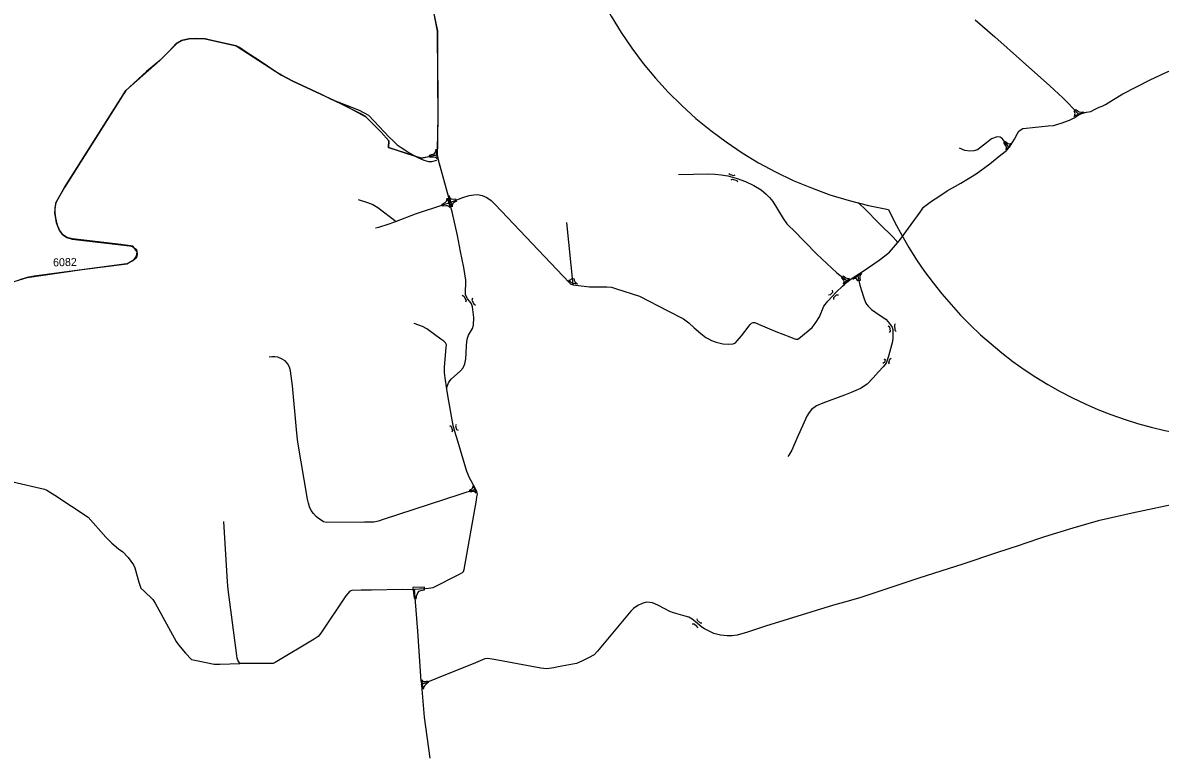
# Model space of a CAD drawing. Extents: x -444937 to -440733, y -1145714 to -1129798.
# Drawn here: x -443173 to -441752, y -1132712 to -1131804 of the extents above; entities that cross this region are included whole.
import ezdxf

# ---------------------------------------------------------------- set-up
doc = ezdxf.new("R2010")
doc.units = 0
for name, color, linetype in [('NIGP_sesuv_uz_P', 7, 'Continuous'), ('Vrstva 12', 7, 'Continuous'), ('Vrstva 75', 7, 'Continuous'), ('Vrstva 8', 7, 'Continuous'), ('Vrstva 84', 7, 'Continuous')]:
    doc.layers.add(name, color=color, linetype=linetype)

msp = doc.modelspace()

# ---------------------------------------------------------------- linework, layer by layer
at = {"layer": 'NIGP_sesuv_uz_P'}
for centre, start, end in [((-442005.1, -1131544.8), 171.1162, 260.1073), ((-441638.4, -1131824.9), 205.1413, 269.9118)]:
    msp.add_arc(centre, 500, start, end, dxfattribs=at)
at = {"layer": 'Vrstva 12'}
msp.add_line((-442485.1, -1132131.6), (-442492.7, -1132053.5), dxfattribs=at)
for points in [[(-441982.7, -1131800.5), (-441958.2, -1131821.9), (-441923.5, -1131852.4), (-441889.7, -1131882.8), (-441873.4, -1131897.8), (-441866.7, -1131904.6), (-441860.5, -1131911.2), (-441854.3, -1131917.8)], [(-442654.8, -1131969.1), (-442667.5, -1131971.9), (-442674.7, -1131973.3), (-442684, -1131970.4), (-442715.8, -1131960), (-442715.4, -1131951.4), (-442724.6, -1131940.9), (-442743.9, -1131921.6), (-442750.9, -1131917.6), (-442761.2, -1131912.4), (-442774.5, -1131905.7), (-442788.4, -1131899.3), (-442800.1, -1131893.4), (-442835.1, -1131877.3), (-442849.1, -1131869.7), (-442856.2, -1131865.4), (-442877.2, -1131851.4), (-442893.4, -1131840.9), (-442901.8, -1131835.2), (-442906.1, -1131832.8), (-442934.3, -1131826.6), (-442944.6, -1131824.4), (-442956.8, -1131823.9), (-442965.2, -1131824.1), (-442974.3, -1131826.4), (-442980.8, -1131830.2), (-442989.2, -1131839.1), (-443001.4, -1131851.4), (-443018.1, -1131865.1), (-443039.1, -1131884.4), (-443043.7, -1131888.6), (-443045.2, -1131890.8), (-443047.1, -1131893.7), (-443052.5, -1131902.5), (-443120.3, -1132010), (-443128.4, -1132023.4), (-443131.1, -1132029.1), (-443132.4, -1132035.3), (-443132.4, -1132041.5), (-443131.5, -1132047.9), (-443129.5, -1132056.9), (-443126.9, -1132063.3), (-443122.7, -1132068.7), (-443117.5, -1132072.3), (-443110.9, -1132074.3), (-443039.3, -1132082.5), (-443035.6, -1132083.6), (-443033.7, -1132084.6), (-443031.1, -1132086.9), (-443030.1, -1132088.9), (-443029.5, -1132093.4), (-443030, -1132095.5), (-443030.9, -1132097.9), (-443035.2, -1132101.5), (-443042.3, -1132105.1), (-443158.1, -1132120.6), (-443167, -1132122.3), (-443176.2, -1132125.1)], [(-442788.4, -1131899.3), (-442752.4, -1131913.4), (-442740.7, -1131919.7), (-442733.4, -1131926.9), (-442714.6, -1131947.1), (-442710, -1131951.8), (-442705, -1131956.7), (-442699.8, -1131960), (-442688.8, -1131966.8), (-442678.8, -1131972.6), (-442671.4, -1131975.8), (-442665.8, -1131977.2), (-442661.5, -1131977.2), (-442655.1, -1131975.8)], [(-441940.7, -1131959.3), (-441949.2, -1131948.5), (-441951.7, -1131946.9), (-441955.8, -1131946.8), (-441959.9, -1131948.2), (-441962.4, -1131949.3), (-441968.7, -1131954.2), (-441979.9, -1131962.7), (-441984.5, -1131963.9), (-441989.6, -1131964.5), (-441995.8, -1131963.6), (-442002.2, -1131960.7)], [(-442353.3, -1131993.5), (-442315.8, -1131992.9), (-442308, -1131993.2), (-442299.9, -1131994.2), (-442291.9, -1131995.5), (-442280.1, -1131998.6), (-442269.5, -1132002.4), (-442259.2, -1132007.5), (-442250.3, -1132012.8), (-442243.8, -1132018.1), (-442239.9, -1132022.3), (-442235.7, -1132027.5), (-442222.5, -1132048.4), (-442217.9, -1132055.2), (-442214.9, -1132058.7), (-442210.3, -1132062.9), (-442180.5, -1132092.9), (-442155.4, -1132116.3), (-442142.2, -1132127)], [(-442753.6, -1132024.9), (-442741.7, -1132028.4), (-442735, -1132031.2), (-442728.9, -1132034.7), (-442706.2, -1132052.2)], [(-442638.9, -1132029.1), (-442646.9, -1132031.7), (-442682.3, -1132043.2), (-442706.2, -1132052.2), (-442715.3, -1132055.6), (-442728.3, -1132059.7), (-442731.9, -1132060.8)], [(-442129.8, -1132118.4), (-442126.9, -1132131.8), (-442122.2, -1132146.4), (-442120, -1132153.6), (-442118.5, -1132155.6), (-442116.6, -1132158), (-442112.5, -1132162.3), (-442101.3, -1132169.5), (-442094.2, -1132174.3), (-442091.4, -1132177.5), (-442086.6, -1132184.2), (-442085.5, -1132187.1), (-442085.7, -1132197.6), (-442086.2, -1132202.2), (-442091.2, -1132220.4), (-442093.8, -1132229.4), (-442097.6, -1132233.7), (-442103.5, -1132240.2), (-442110.4, -1132247.6), (-442117.7, -1132255.5), (-442126.2, -1132261), (-442137.5, -1132265.9), (-442146.1, -1132269.3), (-442173, -1132279.2), (-442181, -1132282.5), (-442187.1, -1132287.1), (-442190.3, -1132290.7), (-442193, -1132295.3), (-442196.4, -1132302.7), (-442205.4, -1132323.2), (-442211.8, -1132338), (-442215.7, -1132344.2), (-442216.9, -1132345.9)], [(-442607.4, -1132386.9), (-442722.3, -1132424.3), (-442728.1, -1132426.6), (-442733.9, -1132427.6), (-442745.6, -1132427.9), (-442792.9, -1132428.2), (-442796.8, -1132427.3), (-442799.9, -1132425.2), (-442803.2, -1132423.2), (-442805.9, -1132420.6), (-442809.4, -1132416.9), (-442812.3, -1132413), (-442814.3, -1132408.4), (-442815.7, -1132403.9), (-442816.9, -1132398.9), (-442828.7, -1132328), (-442829.7, -1132320.8), (-442830.5, -1132311.9), (-442835.7, -1132257.5), (-442838.1, -1132238.7), (-442839.2, -1132234.4), (-442841.8, -1132229.6), (-442844.8, -1132226.4), (-442849.1, -1132223.6), (-442853.7, -1132221.9), (-442857.8, -1132221.2), (-442861.4, -1132221.2), (-442864.9, -1132221.7)], [(-443184.8, -1132377.4), (-443145.3, -1132386.4), (-443142.5, -1132387.7), (-443132.5, -1132394), (-443091, -1132421.4), (-443068.6, -1132446.5), (-443061.1, -1132454), (-443052.8, -1132460.9), (-443047.7, -1132464.7), (-443041, -1132472), (-443037.3, -1132476.4), (-443034, -1132481), (-443032.7, -1132484.6), (-443027.5, -1132502.6), (-443025, -1132510.1), (-443021, -1132513.9), (-443010, -1132524.3), (-443007, -1132528.8), (-442980.8, -1132576.6), (-442978.1, -1132580.9), (-442969.2, -1132591.3), (-442961.6, -1132599.2), (-442953.4, -1132600.9), (-442933.2, -1132605.1), (-442926.2, -1132605), (-442901.2, -1132604.4)], [(-442682.2, -1132512.2), (-442698, -1132511.8), (-442736.9, -1132512.7), (-442742.3, -1132512.8), (-442749.7, -1132512.8), (-442761.5, -1132513.1), (-442764, -1132514), (-442766.3, -1132516.7), (-442768.9, -1132519.9), (-442800.2, -1132566.2), (-442803.5, -1132570.6), (-442808.5, -1132573.7), (-442857.4, -1132602.8), (-442859.5, -1132604), (-442867.6, -1132604.3), (-442901.2, -1132604.4), (-442903.9, -1132599.9), (-442904.6, -1132597.4), (-442905.1, -1132594.4), (-442915.9, -1132512), (-442916.9, -1132502.1), (-442921.4, -1132426.9)], [(-441925.4, -1132456), (-441957.4, -1132466.6), (-441998.1, -1132480.1), (-442034.7, -1132492), (-442053.2, -1132497.6), (-442127, -1132522), (-442146.2, -1132527.7), (-442159.8, -1132531.5), (-442244.7, -1132557.5), (-442267.1, -1132564.9), (-442280.3, -1132568.7), (-442286.5, -1132569.6), (-442292.5, -1132569.7), (-442301, -1132568.7), (-442309.1, -1132566.6), (-442320.9, -1132561.1), (-442324.2, -1132558.9), (-442332, -1132552.1), (-442336.4, -1132548.7), (-442340.5, -1132546.5), (-442344.9, -1132545), (-442359.6, -1132541.1), (-442364.2, -1132539.1), (-442370.3, -1132535.8), (-442379.4, -1132531.3), (-442386, -1132528.6), (-442389.4, -1132527.9), (-442393.4, -1132527.8), (-442398.6, -1132529.1), (-442404.2, -1132531.7), (-442409.7, -1132535.6), (-442413, -1132538.9), (-442454.6, -1132588.8), (-442458.8, -1132593.3), (-442465.6, -1132597.2), (-442474.3, -1132601.4), (-442480.9, -1132604.3), (-442503.5, -1132608.4), (-442509.1, -1132609.4), (-442518, -1132610.8), (-442525.3, -1132609.9), (-442583.6, -1132599.1), (-442591.4, -1132597.8), (-442595.3, -1132598.5), (-442606.9, -1132603.2), (-442655.8, -1132623), (-442675.2, -1132630.7)]]:
    msp.add_lwpolyline(points, dxfattribs=at)
for points in [[(-441853.1, -1131918.1), (-441859.6, -1131921.3), (-441858.4, -1131920.1), (-441858.1, -1131918.7), (-441858, -1131917.4), (-441858.4, -1131916.2), (-441859.2, -1131914.6), (-441857, -1131912.6), (-441854.8, -1131914.3), (-441853, -1131915.2), (-441850.3, -1131915.8), (-441847.1, -1131915.9), (-441848.9, -1131916.5)], [(-442663.7, -1131972.2), (-442664.3, -1131969.7), (-442659.7, -1131968.1), (-442657.8, -1131967), (-442656.7, -1131965.1), (-442656.2, -1131961.9), (-442655.5, -1131969.5), (-442654.6, -1131974.6), (-442655.8, -1131973.1), (-442657, -1131972.5), (-442658.7, -1131972.1)], [(-441944.5, -1131962.9), (-441943.7, -1131961.5), (-441943.6, -1131959.6), (-441944.5, -1131957.9), (-441946.8, -1131953.6), (-441944.9, -1131952.4), (-441941.8, -1131955), (-441940.5, -1131955.5), (-441939, -1131955.3), (-441937.4, -1131954.5), (-441941.1, -1131959.8)], [(-442648.1, -1132033.1), (-442648.4, -1132030.6), (-442644.7, -1132028.6), (-442643.6, -1132027.3), (-442642.9, -1132025.6), (-442642.3, -1132023.2), (-442640.3, -1132029.5), (-442638.9, -1132035), (-442640.4, -1132033.4), (-442641.8, -1132032.7), (-442643.5, -1132032.6)], [(-442149.6, -1132122.8), (-442147.4, -1132125.5), (-442147, -1132127.2), (-442147.2, -1132128.7), (-442147.8, -1132130.3), (-442144.8, -1132127.5), (-442142.8, -1132125.9), (-442139.9, -1132123.6), (-442141.5, -1132123.7), (-442142.8, -1132123.6), (-442144.2, -1132123.2), (-442147.6, -1132120.6)], [(-442129.5, -1132126.6), (-442130.7, -1132124.5), (-442131.8, -1132123.6), (-442133.2, -1132123.4), (-442135.7, -1132124.2), (-442129.2, -1132119.9), (-442124.7, -1132116.8), (-442126.2, -1132118.8), (-442126.8, -1132120.9), (-442126.9, -1132122.8), (-442126.6, -1132125.8)], [(-442488.7, -1132127.2), (-442488.8, -1132127.1), (-442490.5, -1132125.3), (-442489.2, -1132125.4), (-442488.3, -1132125.2), (-442487.8, -1132124.6), (-442487.3, -1132123.8), (-442484.3, -1132123.5), (-442483.7, -1132125.6), (-442482.5, -1132127.9), (-442481.4, -1132129), (-442479.6, -1132130.4), (-442484.6, -1132129.9), (-442487, -1132128.9)], [(-442613.3, -1132390.3), (-442614.5, -1132387.7), (-442612, -1132386.4), (-442610.6, -1132385.2), (-442610.2, -1132384), (-442610, -1132382.2), (-442607.8, -1132387), (-442606.9, -1132389.5), (-442606.5, -1132391.4), (-442607.6, -1132390.1), (-442608.4, -1132389.6), (-442610, -1132389.5)], [(-442673.7, -1132624.5), (-442673.1, -1132625.8), (-442672.1, -1132626.5), (-442670.7, -1132626.6), (-442666.9, -1132625.9), (-442666, -1132628.1), (-442669, -1132630.5), (-442670.5, -1132632), (-442671.5, -1132633.5), (-442672.5, -1132636.1), (-442673.1, -1132630.4)]]:
    msp.add_lwpolyline(points, close=True, dxfattribs=at)
at = {"layer": 'Vrstva 75'}
for points in [[(-442710.9, -1131594.9), (-442706.9, -1131607), (-442692, -1131690.1), (-442685.9, -1131704.1), (-442679.8, -1131715.5), (-442679.7, -1131716.4), (-442682.3, -1131728.8), (-442683.4, -1131734.7), (-442683.4, -1131741), (-442680.5, -1131748.2), (-442676.8, -1131757.3), (-442659.6, -1131790.8), (-442654.9, -1131814.6), (-442654.2, -1131926), (-442654.7, -1131960.9), (-442654.7, -1131968.9), (-442653.6, -1131975.5), (-442651.6, -1131983.4)], [(-443183.1, -1132127.4), (-443167, -1132122.3), (-443098.4, -1132112.3), (-443042.3, -1132105.1), (-443033.2, -1132099.8), (-443030.4, -1132095.8), (-443029.7, -1132090.3), (-443035.2, -1132083.3), (-443049.9, -1132081.2), (-443110.4, -1132074), (-443117.5, -1132072.3), (-443122.7, -1132068.7), (-443126.7, -1132063), (-443130.2, -1132053.9), (-443132.4, -1132041.5), (-443131.1, -1132029.1), (-443120.3, -1132010), (-443045.2, -1131890.8), (-443043.7, -1131888.6), (-443001.4, -1131851.4), (-442979.4, -1131829.3), (-442974.3, -1131826.4), (-442965.2, -1131824.1), (-442952.3, -1131824), (-442944.6, -1131824.4), (-442906.1, -1131832.8), (-442849.1, -1131869.7), (-442835.1, -1131877.3), (-442800.1, -1131893.4), (-442772.4, -1131906.1), (-442743.9, -1131921.6), (-442724.6, -1131940.9), (-442715.4, -1131951.4), (-442715.8, -1131960), (-442702.6, -1131964), (-442674.7, -1131973.3), (-442654.7, -1131968.9)]]:
    msp.add_lwpolyline(points, dxfattribs=at)
at = {"layer": 'Vrstva 8'}
for points in [[(-442704.8, -1131620.8), (-442701.3, -1131638.8), (-442691.9, -1131690.4), (-442685.9, -1131704.4), (-442679.5, -1131716.1), (-442680.7, -1131721.7), (-442682.3, -1131728.8), (-442683.4, -1131734.7), (-442683.4, -1131741), (-442680.5, -1131748.2), (-442676.2, -1131758.2), (-442667.5, -1131775.2), (-442659.6, -1131790.8), (-442654.5, -1131814.4), (-442654.3, -1131843.5), (-442654.2, -1131908.2), (-442654.6, -1131954.8), (-442654.7, -1131968.9), (-442653.6, -1131975.5), (-442640.4, -1132023.4)], [(-441798.4, -1131893), (-441764.2, -1131875.3), (-441744.7, -1131866.2), (-441728.5, -1131859.7), (-441720.1, -1131855.7), (-441709.4, -1131849.4), (-441691, -1131837.5), (-441679.3, -1131828.8), (-441673.8, -1131822.2), (-441676.8, -1131822), (-441676.8, -1131822)], [(-442639.9, -1132028.9), (-442622.9, -1132022.4), (-442615, -1132019.8), (-442609.1, -1132019), (-442604.3, -1132018.6), (-442598.8, -1132019.9), (-442592.9, -1132022.5), (-442587.4, -1132026), (-442582.2, -1132030.9), (-442490.1, -1132128.4), (-442487.9, -1132130.4), (-442485.1, -1132131.6), (-442481.5, -1132131.9), (-442464.6, -1132133.8), (-442458.8, -1132133.9), (-442443.1, -1132133.8), (-442437, -1132134.5), (-442430.8, -1132136.5), (-442402.2, -1132145.7), (-442366.9, -1132163.8), (-442347.3, -1132173.9), (-442340.6, -1132178.7), (-442334, -1132185.1), (-442325.6, -1132192.2), (-442319.3, -1132197.3), (-442315.8, -1132199), (-442312.2, -1132200.9), (-442306.3, -1132202.9), (-442298.1, -1132205.1), (-442290.8, -1132205.4), (-442284.9, -1132205.1), (-442282.2, -1132203.7), (-442280.2, -1132201.4), (-442274.7, -1132195.2), (-442266.3, -1132184.1), (-442264.2, -1132181.2), (-442262, -1132179.1), (-442260.3, -1132178.5), (-442258.1, -1132178.6), (-442253.3, -1132180.4), (-442231.8, -1132189.7), (-442214.5, -1132196.3), (-442209.4, -1132198.3), (-442207, -1132199.1), (-442204.4, -1132199.2), (-442200.9, -1132196.7), (-442186.3, -1132184.5), (-442182.5, -1132179.8), (-442177.1, -1132171.4), (-442171.8, -1132158.2), (-442166.7, -1132151.9), (-442156.5, -1132140.7), (-442148.5, -1132133.1), (-442146.2, -1132131), (-442142, -1132127.4), (-442139.5, -1132125.3), (-442135.4, -1132122.1), (-442123.9, -1132115.1), (-442102.9, -1132100.6), (-442095.7, -1132095.2), (-442089.7, -1132090.7), (-442077.3, -1132076.1), (-442051.4, -1132040.7), (-442047.5, -1132034.5), (-442037.2, -1132027.1), (-442028.3, -1132021), (-442017.6, -1132014.1), (-442000.8, -1132004.3), (-441981.7, -1131992.6), (-441964.6, -1131980.4), (-441950.6, -1131969), (-441943.7, -1131963.7), (-441940, -1131959.6), (-441933.8, -1131949.5), (-441929.8, -1131942.3), (-441928.2, -1131939.4), (-441926.7, -1131938.2), (-441923.1, -1131936.4), (-441919.3, -1131935.7), (-441911.2, -1131934.8), (-441891.7, -1131933), (-441884.9, -1131932.3), (-441875.3, -1131929.6), (-441864.9, -1131925.9), (-441859, -1131922.8), (-441852.7, -1131918.9), (-441848.4, -1131917.1), (-441843.7, -1131915.8), (-441838.2, -1131914.8), (-441833.8, -1131912.6), (-441828.1, -1131909.7), (-441824.2, -1131908.4), (-441819.9, -1131906.4), (-441809.9, -1131900), (-441798.4, -1131893)], [(-442615.1, -1132370.5), (-442616.3, -1132368.1), (-442617.8, -1132364.6), (-442629.1, -1132326.7), (-442632.6, -1132314.4), (-442634.7, -1132307.1), (-442641.5, -1132269.6), (-442642.7, -1132261.8), (-442642.7, -1132259.4), (-442642, -1132256.9), (-442640.4, -1132252.9), (-442637.5, -1132249.2), (-442625.8, -1132238.9), (-442622.5, -1132235.2), (-442620.4, -1132230.2), (-442619.2, -1132223.7), (-442618.5, -1132216.8), (-442618.2, -1132206.9), (-442617.2, -1132199.2), (-442615.6, -1132194.1), (-442611.9, -1132187.8), (-442610.8, -1132186.1), (-442609.3, -1132181.6), (-442609, -1132172.1), (-442610.7, -1132158.7), (-442611.8, -1132155.3), (-442614.1, -1132152), (-442617.1, -1132148.8), (-442619.3, -1132143.3), (-442619.1, -1132125.6), (-442621.4, -1132109.7), (-442625.5, -1132089.9), (-442629.6, -1132069.9), (-442636, -1132040.2), (-442638.4, -1132031.3), (-442640.4, -1132023.4)], [(-442129.3, -1132028.4), (-442121.9, -1132035.4), (-442101.4, -1132055.9), (-442085.7, -1132071.6), (-442079.3, -1132078.4)], [(-442642.7, -1132261.8), (-442645, -1132247.7), (-442645.6, -1132240.9), (-442645.6, -1132234.2), (-442643.6, -1132209.5), (-442643.3, -1132206.3), (-442644.5, -1132203.8), (-442646.6, -1132201.9), (-442650.1, -1132199.3), (-442667.6, -1132186.2), (-442673, -1132183.3), (-442683.5, -1132179.8)], [(-442674.8, -1132626.4), (-442679.1, -1132563.9), (-442683.3, -1132511.2), (-442665.8, -1132510.2), (-442659.9, -1132509.2), (-442627.8, -1132493.1), (-442623.2, -1132490.5), (-442622, -1132489.2), (-442621.2, -1132487), (-442605.8, -1132400.2), (-442605.1, -1132396.1), (-442604.5, -1132392.6), (-442605.4, -1132389.6), (-442606.5, -1132386.9), (-442615.1, -1132370.5)], [(-441723.8, -1132403), (-441786.7, -1132416.5), (-441829.1, -1132426), (-441860.8, -1132435.3), (-441896, -1132446.1), (-441923.4, -1132455.4), (-441925.4, -1132456)], [(-442674.8, -1132626.4), (-442671.2, -1132671.1), (-442663.8, -1132722.3)]]:
    msp.add_lwpolyline(points, dxfattribs=at)
for points in [[(-442640.4, -1132019.7), (-442639, -1132022.6), (-442637.3, -1132023.9), (-442634.9, -1132024.4), (-442632, -1132024.1), (-442631.2, -1132027.5), (-442633.9, -1132028.5), (-442635.3, -1132029.7), (-442636.1, -1132032.3), (-442636.1, -1132034.2), (-442637.8, -1132027.7)], [(-442685.3, -1132509.5), (-442683.6, -1132522.6), (-442681.1, -1132523.5), (-442680.1, -1132518.9), (-442679.2, -1132515.9), (-442677.4, -1132513.9), (-442675.4, -1132512.9), (-442670.5, -1132512.2), (-442670.7, -1132508.7)]]:
    msp.add_lwpolyline(points, close=True, dxfattribs=at)
at = {"layer": 'Vrstva 84'}
for points in [[(-442290.4, -1131992.2), (-442289, -1131993.7), (-442284.3, -1131995), (-442282.8, -1131993.9)], [(-442287.7, -1132000.4), (-442286.1, -1131999.5), (-442280.6, -1132001), (-442279.6, -1132002.9)], [(-442623.7, -1132144.3), (-442621.4, -1132145.7), (-442618.7, -1132150.8), (-442619.5, -1132153.2)], [(-442610.8, -1132148.1), (-442611.4, -1132150.4), (-442609, -1132155.1), (-442607.1, -1132156.6)], [(-442166, -1132143.7), (-442163.6, -1132143.5), (-442160.7, -1132140.5), (-442161, -1132137.9)], [(-442159.2, -1132149.6), (-442159.2, -1132147.3), (-442156, -1132143.9), (-442153.6, -1132144)], [(-442091.5, -1132182.4), (-442089.8, -1132183.8), (-442089.1, -1132189.2), (-442090.4, -1132190.8)], [(-442082.7, -1132180.2), (-442083.7, -1132181.7), (-442083, -1132187.8), (-442081.3, -1132189.5)], [(-442096.8, -1132223.8), (-442095.4, -1132224.8), (-442096.2, -1132228.5), (-442098.2, -1132229.6)], [(-442089.7, -1132230.1), (-442090.5, -1132228.8), (-442089.5, -1132224.2), (-442087.7, -1132223.1)], [(-442639.2, -1132307.1), (-442637.2, -1132308.4), (-442635.7, -1132313.2), (-442636.7, -1132315.2)], [(-442631.2, -1132305.7), (-442632.1, -1132307.3), (-442630.5, -1132312), (-442628.5, -1132312.9)], [(-442330.5, -1132548.4), (-442330.1, -1132550.2), (-442326.2, -1132553.5), (-442324.4, -1132553.5)], [(-442336.2, -1132554.7), (-442333.7, -1132554.8), (-442330.3, -1132557.5), (-442329.8, -1132559.8)]]:
    msp.add_lwpolyline(points, dxfattribs=at)

# ---------------------------------------------------------------- texts
at = {"layer": 'Vrstva 75'}
msp.add_text('6082', height=10, rotation=1.311, dxfattribs=at).set_placement((-443134.6, -1132108.4))
msp.add_text('6082', height=10, rotation=1.311, dxfattribs=at).set_placement((-443134.6, -1132108.4))

doc.saveas('drawing.dxf')
